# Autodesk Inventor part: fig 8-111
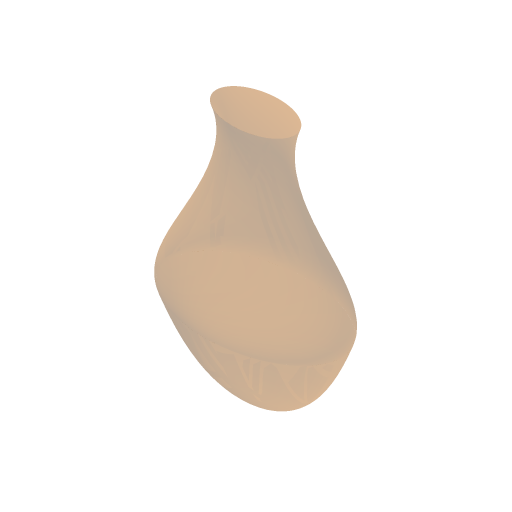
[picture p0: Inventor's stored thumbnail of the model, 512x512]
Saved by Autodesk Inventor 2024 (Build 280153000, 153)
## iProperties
Created: 2004-05
Part Number: fig 8-111
Document SubType Name: Modeling
Designer: CADCIM Technologies
Manufacturer: Standard
Standards Organization: Custom
Density: 1 g/cm^3
Material: Generic
Appearance: Default
Author: CADCIM Technologies
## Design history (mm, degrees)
sketch "Sketch4"
  geometry: 1 further point; 1 other entity
  constraints: 2 other
workplane "Work Plane2"
sketch "Sketch5"
  geometry: 1 further point; 1 other entity
  constraints: 2 other
feature "LoftSrf1" sketch "Sketch5" dims "d4" = 20, "d5" = 110 deg, "d6" = 40, "d7" = 70 deg
patch "Boundary Patch2" dims "d10" = 0, "d11" = 0
patch "Boundary Patch3" dims "d13" = 0, "d14" = 0
body "Srf1"
body "Srf3"
body "Srf4"
other parameters: "d3" = 33.5
